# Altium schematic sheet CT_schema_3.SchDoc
size 400 x 230 mm
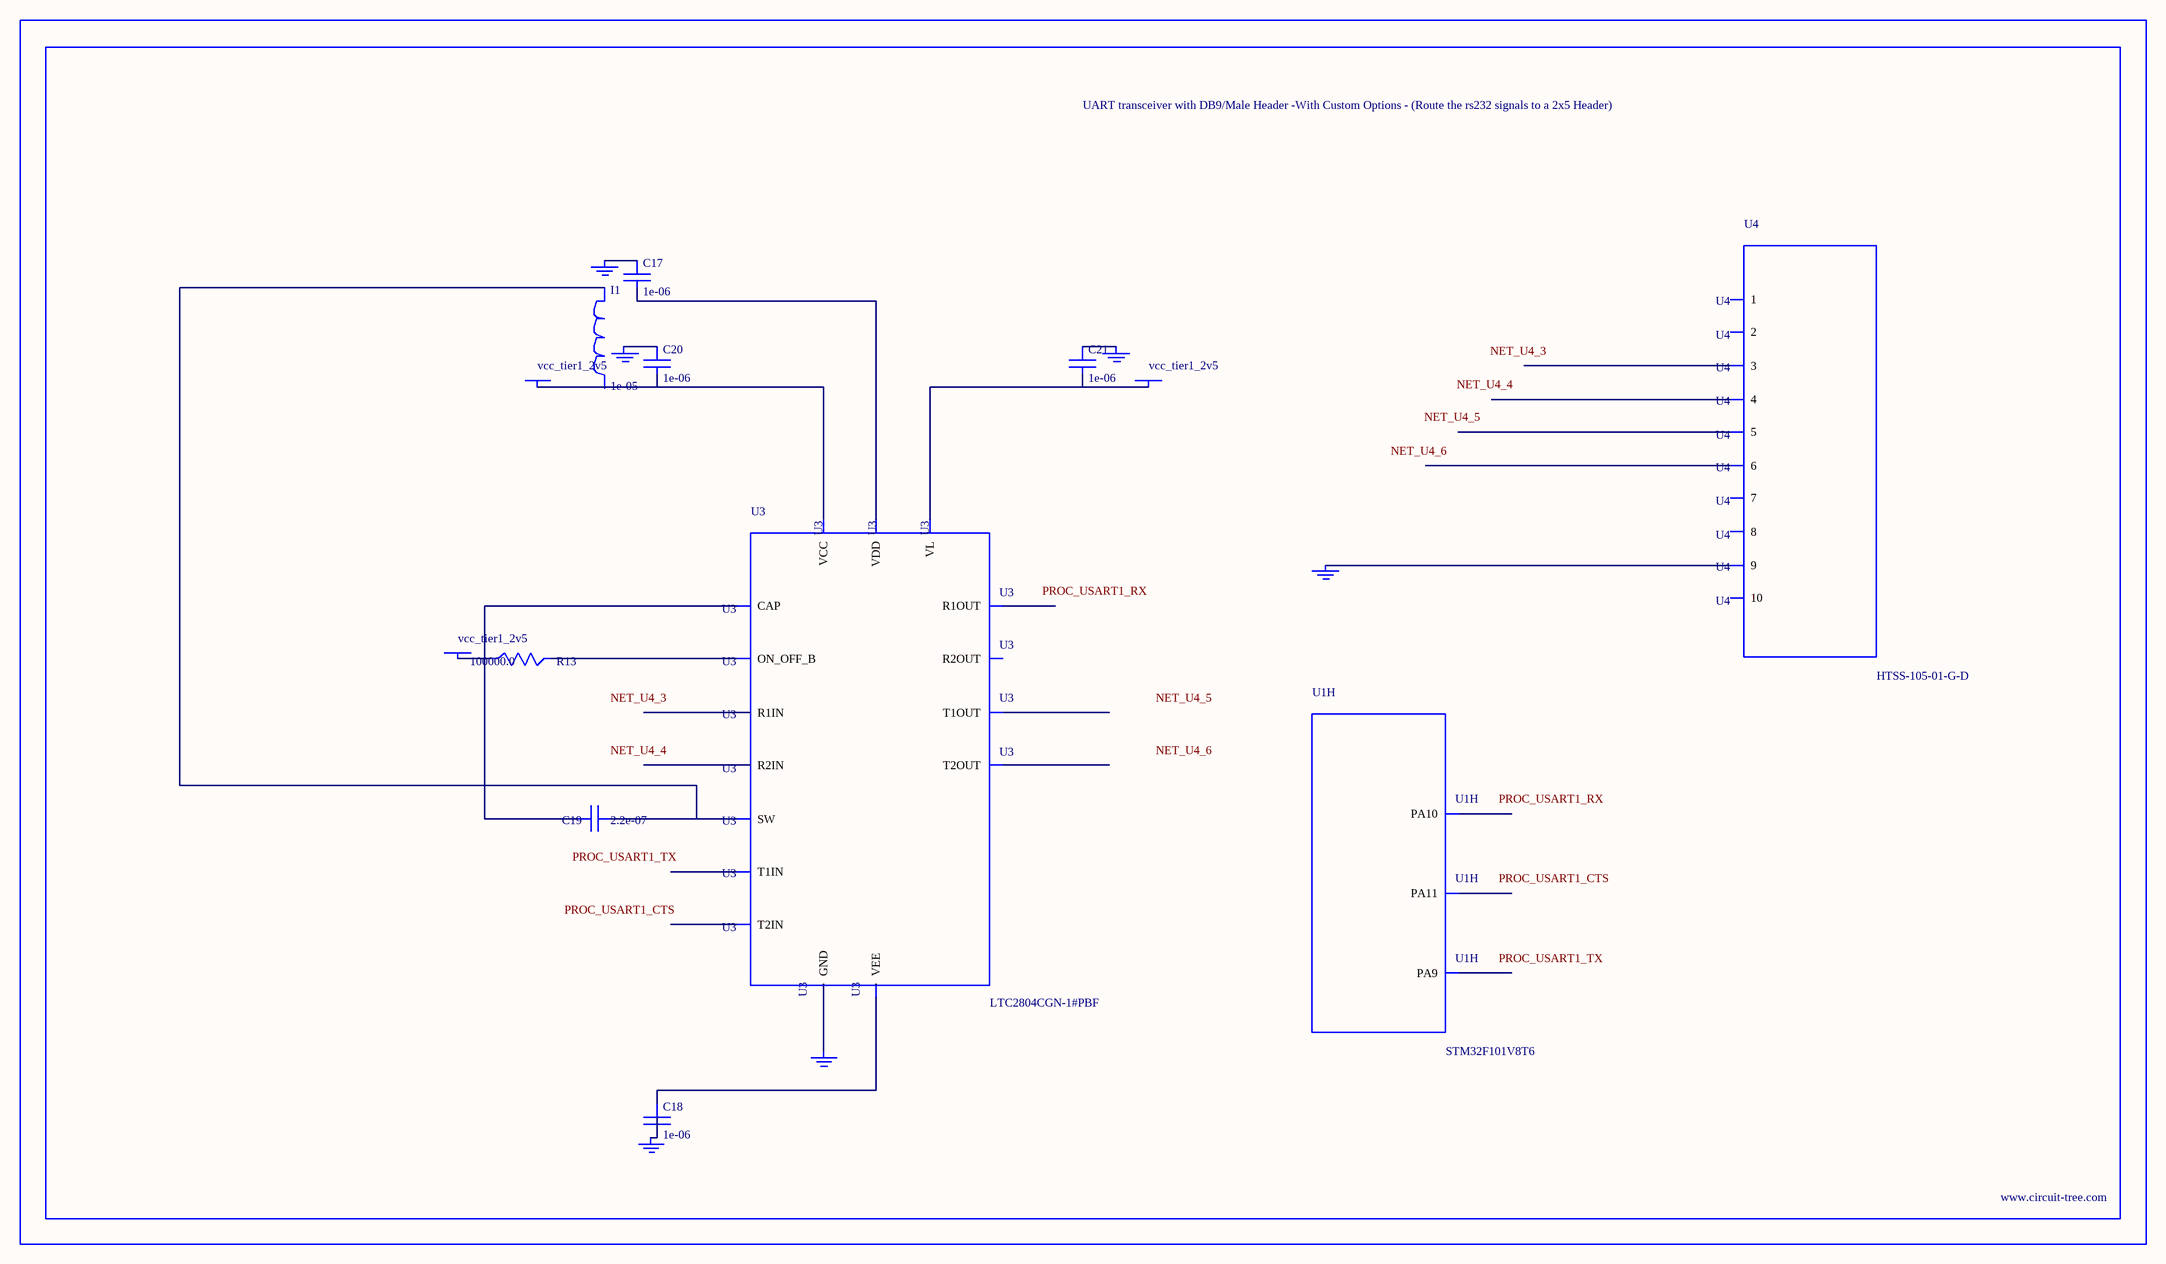
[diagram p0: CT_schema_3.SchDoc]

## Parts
BORDER2  (no value)
C17  1e-06  [C0603]
C18  1e-06  [C0603]
C19  2.2e-07  [C0603]
C20  1e-06  [C0603]
C21  1e-06  [C0603]
GND_INSTANCE_2_0  (no value)
GND_INSTANCE_2_1  (no value)
GND_INSTANCE_2_2  (no value)
GND_INSTANCE_2_3  (no value)
GND_INSTANCE_2_4  (no value)
GND_INSTANCE_2_5  (no value)
I1  1e-05  [L1210]
POWER_INSTANCE_2_0  vcc_tier1_2v5
POWER_INSTANCE_2_1  vcc_tier1_2v5
POWER_INSTANCE_2_2  vcc_tier1_2v5
R13  100000.0  [R0603]
U1  STM32F101V8T6  [LQFP100]  (part H of 10)
U3  LTC2804CGN-1#PBF  [SSOP-16]
U4  HTSS-105-01-G-D  [HTSS-105-01-G-D]

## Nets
NetC17_1: C17.1 GND_INSTANCE_2_1.0(GND)
NetC17_2: C17.2 U3.6(VDD)
NetC18_1: C18.1 U3.9(VEE)
NetC18_2: C18.2 GND_INSTANCE_2_2.0(GND)
NetC19_1: C19.1 I1.1 U3.7(SW)
NetC19_2: C19.2 U3.10(CAP)
NetC20_1: C20.1 GND_INSTANCE_2_0.0(GND)
NetC20_2: C20.2 POWER_INSTANCE_2_0.0(PWR) U3.5(VCC)
NetC21_1: C21.1 GND_INSTANCE_2_3.0(GND)
NetC21_2: C21.2 POWER_INSTANCE_2_2.0(PWR) U3.12(VL)
NetGND_INSTANCE_2_4_0: GND_INSTANCE_2_4.0(GND) U3.8(GND)
NetGND_INSTANCE_2_5_0: GND_INSTANCE_2_5.0(GND) U4.9
NetPOWER_INSTANCE_2_1_0: POWER_INSTANCE_2_1.0(PWR) R13.1
NetR13_2: R13.2 U3.11(ON_OFF_B)

Not connected (* = marked no-connect by the designer): I1 2; U1 68(PA9) 69(PA10) 70(PA11); U3 1(R1IN) 2(R2IN) 3(T1OUT) 4(T2OUT) 13(T2IN) 14(T1IN) 15(R2OUT) 16(R1OUT); U4 1 2 3 4 5 6 7 8 10

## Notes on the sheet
- Labels drawn without touching a wire or pin: NET_U4_3, NET_U4_4, NET_U4_5, NET_U4_6, PROC_USART1_CTS, PROC_USART1_RX, PROC_USART1_TX

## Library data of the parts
BORDER2 = BORDER_PAGE2
C17 C18 C20 C21 = C0603C105K3RACTU
C19 = C0603C224K3RAC
GND_INSTANCE_2_0-GND_INSTANCE_2_5 = GND
I1 = CBC3225T100MR
POWER_INSTANCE_2_0-POWER_INSTANCE_2_2 = PWR
R13 = RC0603JR-07100KL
